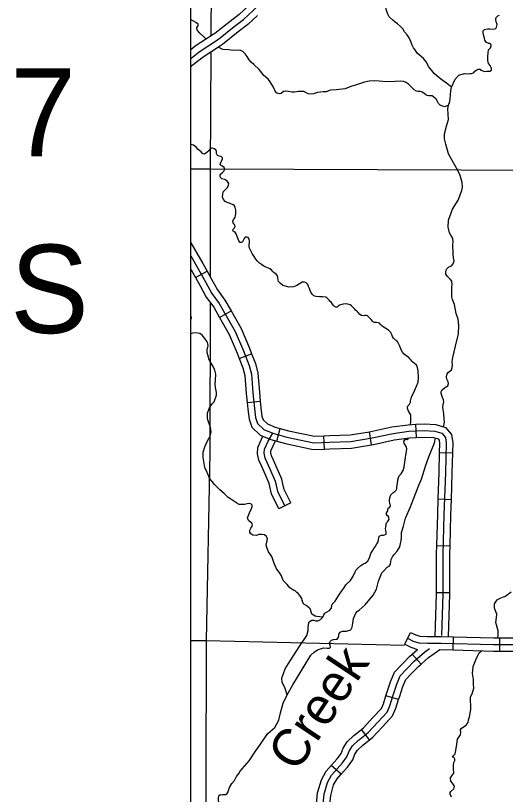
# Model space of a CAD drawing. Extents: x 813775 to 1157140, y 1757555 to 1979907.
# Drawn here: x 908560 to 919670, y 1830487 to 1848131 of the extents above; entities that cross this region are included whole.
import ezdxf

# ---------------------------------------------------------------- set-up
doc = ezdxf.new("R2010")
doc.units = 0
for name, color, linetype in [('Level 31', 7, 'Continuous'), ('Level 32', 7, 'Continuous'), ('Level 35', 7, 'Continuous'), ('Level 45', 7, 'Continuous'), ('Level 5', 7, 'Continuous'), ('R_Draft', 7, 'Continuous')]:
    doc.layers.add(name, color=color, linetype=linetype)

msp = doc.modelspace()

# ---------------------------------------------------------------- linework, layer by layer
at = {"layer": 'Level 31'}
msp.add_line((913206, 1847448), (913206, 1847448), dxfattribs=at)
for points in [[(913839, 1848351), (913631, 1848158), (913427, 1847997), (913077, 1847722), (913042, 1847699)], [(914043, 1848131), (913825, 1847930), (913612, 1847762), (913252, 1847478), (913206, 1847448)], [(913042, 1847699), (912636, 1847435), (912532, 1847351)], [(913206, 1847448), (912813, 1847192), (912560, 1846989), (912532, 1846967)], [(917450, 1834023), (917579, 1833961), (917703, 1833921), (917903, 1833912), (918142, 1833916)], [(918142, 1833916), (918210, 1833916), (919402, 1833885), (920055, 1833881), (920618, 1833885), (920845, 1833912), (921089, 1833965), (921240, 1834010)]]:
    msp.add_lwpolyline(points, dxfattribs=at)
at = {"layer": 'Level 32'}
for p, q in [((912640, 1842196), (912902, 1842341)), ((913186, 1841292), (913447, 1841440)), ((913633, 1840363), (913913, 1840469)), ((913810, 1839369), (914108, 1839399)), ((917656, 1838573), (917641, 1838872)), ((914484, 1838488), (914562, 1838778)), ((916632, 1838408), (916583, 1838704)), ((915564, 1838310), (915552, 1838610)), ((918169, 1838235), (918469, 1838227)), ((918138, 1837180), (918438, 1837171)), ((918105, 1836124), (918405, 1836116)), ((918100, 1835064), (918400, 1835064)), ((917385, 1833888), (917516, 1834158)), ((918482, 1833759), (918489, 1834059)), ((919540, 1833734), (919542, 1834034)), ((917755, 1833439), (917556, 1833664)), ((917247, 1832636), (916960, 1832723)), ((916589, 1831725), (916404, 1831961)), ((915943, 1830942), (915719, 1831141))]:
    msp.add_line(p, q, dxfattribs=at)
for points in [[(912725, 1847313), (913164, 1847600), (913519, 1847880), (913728, 1848044), (913959, 1848257), (914070, 1848377), (914460, 1848793), (914828, 1849122), (915197, 1849397), (915490, 1849553), (916023, 1849828), (916848, 1850202), (917260, 1850408), (917789, 1850804), (918401, 1851252), (919258, 1851906), (919871, 1852368), (920115, 1852546), (920266, 1852639), (920426, 1852726), (920697, 1852828)], [(912532, 1847159), (912725, 1847313)], [(912532, 1842983), (912804, 1842518), (912902, 1842341)], [(912532, 1842686), (912674, 1842444), (912874, 1842084), (913011, 1841835)], [(912532, 1842389), (912544, 1842369), (912640, 1842196)], [(912902, 1842341), (913005, 1842156), (913138, 1841916), (913306, 1841687), (913447, 1841440)], [(912640, 1842196), (912743, 1842011), (912885, 1841754), (913054, 1841524), (913186, 1841292)], [(913011, 1841835), (913180, 1841605), (913540, 1840974), (913726, 1840539), (913855, 1840201), (913908, 1840005), (913939, 1839583), (913975, 1839228), (914001, 1839023)], [(913447, 1841440), (913674, 1841041), (913865, 1840595), (913913, 1840469)], [(913186, 1841292), (913405, 1840907), (913587, 1840483), (913633, 1840363)], [(913913, 1840469), (913998, 1840248), (914057, 1840031), (914089, 1839596), (914108, 1839399)], [(913633, 1840363), (913712, 1840154), (913760, 1839980), (913790, 1839570), (913810, 1839369)], [(914108, 1839399), (914124, 1839245), (914148, 1839059), (914179, 1838975), (914276, 1838879), (914444, 1838810), (914562, 1838778)], [(913810, 1839369), (913826, 1839211), (913855, 1838987), (913920, 1838809), (914107, 1838624), (914347, 1838525), (914484, 1838488)], [(914001, 1839023), (914049, 1838892), (914191, 1838752), (914396, 1838667), (914715, 1838581), (915324, 1838450), (915683, 1838465), (916163, 1838483), (916647, 1838563), (917122, 1838665), (917477, 1838714), (917828, 1838732), (918067, 1838718), (918227, 1838670), (918307, 1838576), (918325, 1838443), (918307, 1837776)], [(916583, 1838704), (916619, 1838710), (917096, 1838813), (917463, 1838863), (917641, 1838872)], [(917641, 1838872), (917828, 1838882), (918094, 1838867), (918313, 1838800), (918450, 1838640), (918475, 1838451), (918469, 1838227)], [(914562, 1838778), (914751, 1838726), (915336, 1838600), (915552, 1838610)], [(915552, 1838610), (915677, 1838615), (916148, 1838632), (916583, 1838704)], [(916632, 1838408), (916675, 1838415), (917148, 1838517), (917491, 1838565), (917656, 1838573)], [(917656, 1838573), (917827, 1838582), (918041, 1838570), (918142, 1838539), (918164, 1838512), (918175, 1838435), (918169, 1838235)], [(914484, 1838488), (914680, 1838435), (915311, 1838299), (915564, 1838310)], [(915564, 1838310), (915689, 1838315), (916178, 1838333), (916632, 1838408)], [(918169, 1838235), (918157, 1837781), (918138, 1837180)], [(918469, 1838227), (918457, 1837772), (918438, 1837171)], [(918307, 1837776), (918276, 1836820), (918250, 1835927), (918250, 1835020), (918223, 1834085)], [(918138, 1837180), (918126, 1836825), (918105, 1836124)], [(918438, 1837171), (918426, 1836816), (918405, 1836116)], [(918105, 1836124), (918100, 1835929), (918100, 1835064)], [(918405, 1836116), (918400, 1835925), (918400, 1835064)], [(918100, 1835064), (918100, 1835023), (918072, 1834065)], [(918400, 1835064), (918400, 1835018), (918372, 1834062)], [(917516, 1834158), (917635, 1834101), (917730, 1834070), (917905, 1834062), (918140, 1834066), (918211, 1834066), (918489, 1834059)], [(918489, 1834059), (919404, 1834035), (919542, 1834034)], [(919542, 1834034), (920054, 1834031), (920596, 1834035)], [(915514, 1830054), (915559, 1830494), (915634, 1830760), (915728, 1830925), (915972, 1831200), (916074, 1831342), (916123, 1831466), (916198, 1831586), (916327, 1831710), (916553, 1831888), (916775, 1832123), (916984, 1832350), (917046, 1832490), (917122, 1832739), (917206, 1832988), (917281, 1833170), (917441, 1833339), (917601, 1833503), (917832, 1833708), (917950, 1833789)], [(917385, 1833888), (917523, 1833821), (917678, 1833772)], [(917556, 1833664), (917678, 1833772)], [(917755, 1833439), (917925, 1833589), (918183, 1833767)], [(918183, 1833767), (918482, 1833759)], [(918482, 1833759), (919399, 1833735), (919540, 1833734)], [(916960, 1832723), (916979, 1832785), (917066, 1833041), (917153, 1833253), (917333, 1833443), (917497, 1833612), (917556, 1833664)], [(919540, 1833734), (920055, 1833731), (920598, 1833735)], [(917247, 1832636), (917264, 1832693), (917346, 1832935), (917409, 1833087), (917550, 1833235), (917705, 1833395), (917755, 1833439)], [(916404, 1831961), (916452, 1831999), (916666, 1832226), (916857, 1832433), (916905, 1832542), (916960, 1832723)], [(916589, 1831725), (916655, 1831777), (916885, 1832021), (917111, 1832266), (917187, 1832438), (917247, 1832636)], [(915719, 1831141), (915854, 1831294), (915941, 1831415), (915988, 1831534), (916081, 1831681), (916228, 1831823), (916404, 1831961)], [(915943, 1830942), (916089, 1831106), (916206, 1831270), (916257, 1831397), (916315, 1831490), (916426, 1831597), (916589, 1831725)], [(915366, 1830077), (915411, 1830522), (915495, 1830818), (915605, 1831012), (915719, 1831141)], [(915664, 1830047), (915707, 1830465), (915774, 1830702), (915850, 1830837), (915943, 1830942)]]:
    msp.add_lwpolyline(points, dxfattribs=at)
at = {"layer": 'Level 35'}
for points in [[(917117, 1848023), (917032, 1848102), (917008, 1848150), (916972, 1848247), (916940, 1848371), (916911, 1848473), (916858, 1848541), (916807, 1848599), (916776, 1848657), (916773, 1848727), (916814, 1848810), (916831, 1848902), (916829, 1848977), (916829, 1849016), (916834, 1849064), (916826, 1849108)], [(912670, 1847833), (912673, 1847859), (912699, 1847897), (912699, 1847936), (912651, 1847977), (912544, 1848031), (912532, 1848038)], [(919480, 1847929), (919463, 1847988), (919449, 1848046), (919456, 1848090), (919495, 1848126), (919536, 1848141)], [(917766, 1847193), (917713, 1847238), (917664, 1847276), (917626, 1847354), (917587, 1847400), (917558, 1847461), (917526, 1847545), (917490, 1847623), (917444, 1847693), (917383, 1847764), (917340, 1847832), (917291, 1847882), (917224, 1847941), (917170, 1847982), (917117, 1848023)], [(918533, 1846689), (918616, 1846783), (918739, 1846817), (918802, 1846814), (918873, 1846819), (918897, 1846822), (918936, 1846831), (918962, 1846851), (918979, 1846868), (919020, 1846904), (919054, 1846919), (919093, 1846914), (919112, 1846894), (919202, 1846865), (919248, 1846868), (919277, 1846868), (919316, 1846873), (919350, 1846897), (919354, 1846943), (919323, 1847001), (919287, 1847047), (919270, 1847110), (919270, 1847202), (919289, 1847353), (919333, 1847403), (919347, 1847447), (919345, 1847466), (919333, 1847486), (919311, 1847498), (919294, 1847500), (919241, 1847520), (919202, 1847573), (919190, 1847651), (919173, 1847692), (919163, 1847748), (919163, 1847786), (919192, 1847815), (919260, 1847830), (919316, 1847828), (919393, 1847820), (919449, 1847840), (919466, 1847869), (919480, 1847929)], [(912884, 1847596), (912827, 1847646), (912738, 1847729), (912684, 1847792), (912670, 1847833)], [(913623, 1847344), (913493, 1847341), (913394, 1847353), (913258, 1847360), (913154, 1847414)], [(914640, 1846412), (914582, 1846363), (914529, 1846358), (914478, 1846380), (914447, 1846421), (914408, 1846511), (914360, 1846591), (914333, 1846629), (914294, 1846683), (914238, 1846736), (914185, 1846784), (914142, 1846833), (914081, 1846910), (913960, 1847022), (913902, 1847078), (913858, 1847131), (913810, 1847204), (913766, 1847262), (913713, 1847318), (913665, 1847342), (913623, 1847344)], [(918446, 1846512), (918333, 1846599), (918260, 1846655), (918170, 1846723), (918057, 1846818), (917998, 1846890), (917928, 1846978), (917877, 1847079), (917810, 1847159), (917766, 1847193)], [(917167, 1846637), (916974, 1846632), (916807, 1846645), (916705, 1846654), (916581, 1846645), (916472, 1846623), (916293, 1846560)], [(918379, 1846099), (918298, 1846063), (918242, 1846077), (918191, 1846104), (918150, 1846140), (918128, 1846182), (918097, 1846235), (918046, 1846283), (918005, 1846312), (917930, 1846312), (917898, 1846317), (917862, 1846334), (917818, 1846373), (917783, 1846396), (917743, 1846407), (917688, 1846407), (917655, 1846418), (917598, 1846451), (917533, 1846514), (917472, 1846577), (917404, 1846620), (917361, 1846640), (917283, 1846642), (917167, 1846637)], [(918335, 1845628), (918377, 1845778), (918369, 1845901), (918360, 1846020), (918379, 1846099), (918406, 1846182), (918413, 1846243), (918429, 1846424), (918446, 1846512), (918533, 1846689)], [(916293, 1846560), (916167, 1846521), (916032, 1846470), (915831, 1846446), (915710, 1846441), (915673, 1846436), (915613, 1846402), (915535, 1846400), (915472, 1846397), (915409, 1846385), (915317, 1846356), (915238, 1846351), (915194, 1846359)], [(915194, 1846359), (915100, 1846409), (915027, 1846414), (914977, 1846412), (914887, 1846397), (914831, 1846392), (914744, 1846412), (914679, 1846419), (914640, 1846412)], [(918695, 1844241), (918687, 1844346), (918641, 1844510), (918587, 1844620), (918457, 1844862), (918379, 1844999), (918316, 1845219), (918286, 1845339), (918289, 1845449), (918335, 1845628)], [(913207, 1844743), (913200, 1844762), (913229, 1844830), (913253, 1844885), (913253, 1844910), (913221, 1844941), (913175, 1844944), (913139, 1844960), (913115, 1845007), (913115, 1845053), (913098, 1845087), (913061, 1845111), (913023, 1845128), (913011, 1845125), (912977, 1845113), (912953, 1845077), (912897, 1845026), (912844, 1844992), (912810, 1845002), (912766, 1845043), (912698, 1845099), (912655, 1845150), (912597, 1845196), (912532, 1845212)], [(913270, 1844141), (913362, 1844232), (913391, 1844280), (913398, 1844329), (913362, 1844382), (913308, 1844418), (913238, 1844433), (913209, 1844462), (913197, 1844493), (913202, 1844532), (913246, 1844566), (913284, 1844605), (913308, 1844651), (913289, 1844690), (913241, 1844724), (913207, 1844743)], [(918367, 1843336), (918382, 1843497), (918467, 1843745), (918594, 1843950), (918677, 1844166), (918695, 1844241)], [(913496, 1843844), (913424, 1843873), (913361, 1843897), (913315, 1843920), (913276, 1843962), (913256, 1844018), (913258, 1844084), (913270, 1844141)], [(913522, 1843399), (913508, 1843412), (913492, 1843432), (913486, 1843469), (913499, 1843509), (913537, 1843556), (913548, 1843603), (913556, 1843643), (913554, 1843724), (913544, 1843780), (913526, 1843820), (913496, 1843844)], [(913534, 1843229), (913492, 1843243), (913486, 1843263), (913492, 1843292), (913522, 1843323), (913539, 1843355), (913535, 1843382), (913522, 1843399)], [(918458, 1842039), (918452, 1842117), (918413, 1842161), (918355, 1842217), (918318, 1842271), (918316, 1842327), (918330, 1842384), (918379, 1842428), (918450, 1842462), (918484, 1842506), (918504, 1842572), (918489, 1842641), (918487, 1842726), (918482, 1842812), (918476, 1842865), (918479, 1842947), (918484, 1843005), (918477, 1843071), (918465, 1843113), (918433, 1843157), (918404, 1843208), (918367, 1843336)], [(913854, 1842936), (913866, 1842988), (913867, 1843017), (913858, 1843068), (913837, 1843100), (913804, 1843112), (913769, 1843109), (913744, 1843081), (913719, 1843036), (913704, 1843005), (913679, 1842987), (913655, 1842990), (913626, 1843030), (913587, 1843125), (913560, 1843186), (913534, 1843229)], [(914296, 1842408), (914218, 1842441), (914188, 1842456), (914138, 1842488), (914091, 1842521), (914046, 1842569), (914012, 1842614), (913973, 1842675), (913923, 1842741), (913886, 1842815), (913868, 1842858), (913854, 1842898), (913854, 1842936)], [(914516, 1842137), (914510, 1842200), (914499, 1842235), (914478, 1842267), (914448, 1842290), (914414, 1842312), (914397, 1842325), (914385, 1842342), (914361, 1842371), (914325, 1842393), (914296, 1842408)], [(915059, 1842090), (915000, 1842056), (914939, 1842013), (914862, 1841983), (914767, 1841976), (914623, 1842013), (914559, 1842070), (914525, 1842107), (914516, 1842137)], [(915673, 1841686), (915622, 1841733), (915597, 1841750), (915525, 1841760), (915454, 1841762), (915379, 1841768), (915327, 1841784), (915284, 1841823), (915250, 1841878), (915228, 1841949), (915204, 1841994), (915186, 1842042), (915149, 1842078), (915109, 1842091), (915059, 1842090)], [(918457, 1841762), (918452, 1841843), (918457, 1841977), (918458, 1842039)], [(916269, 1841457), (916244, 1841487), (916223, 1841511), (916176, 1841554), (916148, 1841576), (916099, 1841593), (916043, 1841599), (915992, 1841593), (915910, 1841574), (915884, 1841554), (915857, 1841528), (915824, 1841524), (915795, 1841538), (915769, 1841564), (915749, 1841596), (915727, 1841627), (915698, 1841657), (915673, 1841686)], [(918477, 1840383), (918540, 1840638), (918602, 1840920), (918609, 1841111), (918597, 1841255), (918550, 1841382), (918511, 1841588), (918472, 1841695), (918457, 1841762)], [(912532, 1841239), (912536, 1841244), (912551, 1841282), (912544, 1841316), (912532, 1841331)], [(916813, 1841162), (916786, 1841171), (916745, 1841174), (916701, 1841175), (916676, 1841187), (916653, 1841209), (916624, 1841244), (916601, 1841272), (916575, 1841301), (916545, 1841328), (916521, 1841337), (916479, 1841337), (916446, 1841329), (916407, 1841336), (916370, 1841362), (916331, 1841404), (916297, 1841437), (916269, 1841457)], [(917308, 1840555), (917276, 1840641), (917228, 1840731), (917215, 1840754), (917198, 1840770), (917180, 1840779), (917154, 1840801), (917132, 1840824), (917107, 1840859), (917086, 1840919), (917067, 1840949), (917017, 1841003), (916954, 1841039), (916894, 1841077), (916862, 1841108), (916838, 1841132), (916813, 1841162)], [(912903, 1840738), (912849, 1840815), (912793, 1840892), (912737, 1840928), (912640, 1840945), (912573, 1840936), (912532, 1840921)], [(912936, 1840389), (912907, 1840495), (912907, 1840556), (912926, 1840653), (912924, 1840697), (912914, 1840726), (912903, 1840738)], [(917475, 1840384), (917417, 1840422), (917371, 1840462), (917334, 1840506), (917308, 1840555)], [(913064, 1839383), (913117, 1839529), (913120, 1839590), (913093, 1839702), (913083, 1839791), (913093, 1839869), (913100, 1840007), (913079, 1840097), (913042, 1840179), (912972, 1840293), (912945, 1840344), (912936, 1840389)], [(917692, 1840030), (917689, 1840086), (917679, 1840155), (917652, 1840209), (917603, 1840253), (917570, 1840276), (917554, 1840293), (917528, 1840326), (917503, 1840357), (917475, 1840384)], [(918360, 1839745), (918379, 1839793), (918374, 1839834), (918340, 1839893), (918330, 1839950), (918347, 1840013), (918377, 1840052), (918443, 1840106), (918465, 1840160), (918467, 1840211), (918462, 1840295), (918477, 1840383)], [(917585, 1839577), (917656, 1839735), (917692, 1839824), (917700, 1839925), (917695, 1839982), (917692, 1840030)], [(918257, 1838817), (918274, 1838842), (918291, 1838920), (918281, 1838996), (918269, 1839111), (918252, 1839256), (918257, 1839312), (918272, 1839383), (918264, 1839427), (918242, 1839478), (918210, 1839571), (918210, 1839611), (918228, 1839647), (918291, 1839694), (918360, 1839745)], [(917523, 1838926), (917521, 1838998), (917526, 1839043), (917521, 1839086), (917512, 1839108), (917482, 1839153), (917461, 1839192), (917451, 1839232), (917451, 1839261), (917464, 1839299), (917492, 1839331), (917516, 1839371), (917520, 1839387), (917518, 1839406), (917521, 1839436), (917532, 1839461), (917557, 1839522), (917585, 1839577)], [(912912, 1838497), (912977, 1838605), (912999, 1838692), (912984, 1838801), (912914, 1838998), (912914, 1839121), (912948, 1839228), (913016, 1839335), (913064, 1839383)], [(917516, 1838866), (917523, 1838926)], [(917409, 1838181), (917425, 1838255), (917435, 1838314), (917422, 1838368), (917396, 1838406), (917372, 1838438), (917369, 1838480), (917386, 1838517), (917408, 1838532), (917443, 1838530), (917464, 1838540), (917470, 1838562)], [(917766, 1837631), (917866, 1837943), (917932, 1838136), (918064, 1838455), (918086, 1838556)], [(912967, 1837635), (912904, 1837777), (912851, 1837896), (912817, 1838119), (912817, 1838243), (912849, 1838359), (912912, 1838497)], [(917308, 1837748), (917348, 1837825), (917374, 1837908), (917391, 1838014), (917406, 1838123), (917409, 1838181)], [(913699, 1837051), (913633, 1837054), (913580, 1837088), (913507, 1837129), (913439, 1837172), (913381, 1837216), (913287, 1837303), (913190, 1837388), (913069, 1837504), (913016, 1837572), (912967, 1837635)], [(917223, 1837533), (917230, 1837611), (917244, 1837667), (917263, 1837704), (917308, 1837748)], [(917306, 1836235), (917311, 1836317), (917316, 1836422), (917355, 1836567), (917406, 1836745), (917514, 1837000), (917702, 1837489), (917766, 1837631)], [(917048, 1836995), (917063, 1837032), (917063, 1837038), (917045, 1837070), (917042, 1837145), (917051, 1837217), (917071, 1837272), (917115, 1837317), (917165, 1837352), (917189, 1837380), (917208, 1837413), (917208, 1837464), (917223, 1837533)], [(913699, 1837051), (913694, 1837051)], [(914245, 1836134), (914262, 1836201), (914274, 1836274), (914250, 1836330), (914202, 1836364), (914144, 1836376), (914076, 1836378), (914025, 1836354), (913940, 1836357), (913899, 1836388), (913875, 1836427), (913870, 1836475), (913897, 1836521), (913921, 1836550), (913931, 1836594), (913918, 1836630), (913885, 1836657), (913839, 1836691), (913822, 1836754), (913863, 1836863), (913911, 1836962), (913928, 1837013), (913923, 1837042), (913894, 1837069), (913851, 1837074), (913812, 1837068), (913751, 1837057), (913699, 1837051)], [(916963, 1836618), (916969, 1836638), (916998, 1836662), (917007, 1836684), (917030, 1836725), (917028, 1836750), (917026, 1836764), (917023, 1836771), (917009, 1836788), (916990, 1836803), (916976, 1836827), (916973, 1836864), (916999, 1836908), (917005, 1836949), (917023, 1836976), (917048, 1836995)], [(916785, 1836211), (916793, 1836258), (916796, 1836289), (916802, 1836320), (916821, 1836345), (916856, 1836361), (916901, 1836361), (916928, 1836365), (916962, 1836384), (916965, 1836406), (916964, 1836428), (916958, 1836468), (916952, 1836512), (916954, 1836538), (916963, 1836577), (916963, 1836618)], [(916901, 1835547), (916986, 1835633), (917030, 1835660), (917064, 1835701), (917074, 1835760), (917077, 1835807), (917106, 1835868), (917152, 1835931), (917216, 1835995), (917272, 1836098), (917292, 1836169), (917306, 1836235)], [(914630, 1835336), (914592, 1835439), (914553, 1835499), (914473, 1835611), (914415, 1835737), (914371, 1835880), (914294, 1835982), (914255, 1836079), (914245, 1836134)], [(916487, 1835726), (916528, 1835757), (916546, 1835772), (916594, 1835871), (916619, 1835941), (916651, 1836007), (916687, 1836056), (916717, 1836096), (916755, 1836161), (916785, 1836211)], [(916048, 1835234), (916153, 1835332), (916215, 1835434), (916259, 1835533), (916283, 1835576), (916311, 1835608), (916391, 1835673), (916410, 1835691), (916447, 1835709), (916487, 1835726)], [(916356, 1834659), (916492, 1834778), (916668, 1835003), (916747, 1835137), (916791, 1835319), (916869, 1835507), (916901, 1835547)], [(915066, 1834851), (915049, 1834926), (915006, 1834996), (914967, 1835035), (914940, 1835064), (914904, 1835096), (914870, 1835103), (914780, 1835166), (914720, 1835241), (914630, 1835336)], [(915197, 1834246), (915202, 1834345), (915221, 1834394), (915278, 1834438), (915326, 1834433), (915361, 1834421), (915412, 1834421), (915476, 1834451), (915525, 1834502), (915551, 1834558), (915571, 1834592), (915630, 1834624), (915681, 1834654), (915723, 1834707), (915730, 1834771), (915740, 1834796), (915808, 1834867), (915845, 1834923), (915908, 1835021), (915960, 1835102), (916004, 1835158), (916048, 1835234)], [(919498, 1834034), (919506, 1834103), (919506, 1834196), (919454, 1834380), (919467, 1834494), (919472, 1834571), (919418, 1834709), (919418, 1834802), (919480, 1834892), (919552, 1834934), (919625, 1834960), (919656, 1834973), (919803, 1835075)], [(915525, 1834502), (915393, 1834514), (915357, 1834524), (915279, 1834572), (915250, 1834674), (915245, 1834686), (915221, 1834715), (915149, 1834764), (915095, 1834800), (915066, 1834851), (915069, 1834887)], [(915681, 1833803), (915703, 1833826), (915693, 1833868), (915683, 1833915), (915693, 1833954), (915723, 1833983), (915771, 1833993), (915855, 1834005), (915881, 1834047), (915899, 1834130), (915921, 1834162), (915977, 1834184), (916062, 1834186), (916165, 1834216), (916197, 1834279), (916209, 1834367), (916221, 1834473), (916251, 1834541), (916275, 1834595), (916317, 1834639), (916356, 1834659)], [(914721, 1832743), (914674, 1832886), (914608, 1833028), (914598, 1833118), (914677, 1833334), (914784, 1833512), (915009, 1833855), (915163, 1834087), (915197, 1834200), (915197, 1834246)], [(914721, 1832743), (914845, 1832971), (915080, 1833358), (915254, 1833642), (915334, 1833713), (915405, 1833762), (915540, 1833806), (915623, 1833799), (915681, 1833803)], [(918917, 1832765), (918950, 1832893), (918948, 1832981), (918943, 1833087), (918922, 1833224), (918938, 1833387), (919000, 1833537), (919033, 1833620), (919077, 1833693), (919127, 1833742)], [(914157, 1831693), (914283, 1831867), (914442, 1832006), (914530, 1832170), (914567, 1832332), (914628, 1832555), (914721, 1832743)], [(918544, 1831480), (918568, 1831628), (918586, 1831737), (918650, 1831833), (918658, 1831900), (918653, 1831949), (918671, 1831986), (918780, 1832053), (918826, 1832113), (918829, 1832177), (918857, 1832245), (918888, 1832410), (918886, 1832516), (918881, 1832589), (918878, 1832700), (918917, 1832765)], [(913568, 1830890), (913631, 1830972), (913648, 1831003), (913861, 1831246), (914003, 1831463), (914098, 1831605), (914157, 1831693)], [(918449, 1830426), (918418, 1830494), (918415, 1830530), (918433, 1830556), (918500, 1830615), (918511, 1830675), (918469, 1830740), (918431, 1830789), (918420, 1830859), (918451, 1830908), (918503, 1830967), (918493, 1831076), (918495, 1831154), (918498, 1831213), (918519, 1831255), (918519, 1831288), (918506, 1831312), (918487, 1831327), (918472, 1831340), (918475, 1831356), (918498, 1831377), (918526, 1831405), (918539, 1831444), (918544, 1831480)], [(913374, 1830531), (913408, 1830640), (913462, 1830731), (913525, 1830803), (913568, 1830890)], [(913050, 1829920), (913112, 1830001), (913140, 1830066), (913156, 1830137), (913171, 1830184), (913174, 1830246), (913166, 1830370), (913165, 1830416), (913172, 1830445), (913190, 1830475), (913212, 1830481), (913256, 1830482), (913323, 1830487), (913358, 1830509), (913374, 1830531)]]:
    msp.add_lwpolyline(points, dxfattribs=at)
at = {"layer": 'Level 45'}
msp.add_line((914801, 1837089), (914532, 1836957), dxfattribs=at)
for points in [[(914134, 1837933), (914075, 1838060), (914044, 1838206), (914058, 1838346), (914169, 1838599)], [(914667, 1837023), (914507, 1837347), (914476, 1837494), (914458, 1837578), (914334, 1837858), (914218, 1838107), (914196, 1838214), (914205, 1838307), (914285, 1838490), (914396, 1838667)], [(914406, 1838059), (914361, 1838155), (914347, 1838222), (914352, 1838269), (914452, 1838497)], [(914801, 1837089), (914650, 1837397), (914622, 1837525), (914601, 1837625), (914470, 1837920), (914406, 1838059)], [(914532, 1836957), (914364, 1837298), (914329, 1837463), (914314, 1837532), (914197, 1837796), (914134, 1837933)]]:
    msp.add_lwpolyline(points, dxfattribs=at)
at = {"layer": 'Level 5'}
for points in [[(913038, 1855215), (912991, 1847666)], [(912988, 1847306), (912972, 1844659)], [(912532, 1844657), (912972, 1844659)], [(912972, 1844659), (912970, 1842219)], [(912972, 1844659), (920561, 1844630)], [(912970, 1841638), (912967, 1838234), (912882, 1833970)], [(912532, 1833973), (912882, 1833970)], [(912882, 1833970), (912871, 1827400)], [(912882, 1833970), (917377, 1833868)]]:
    msp.add_lwpolyline(points, dxfattribs=at)
at = {"layer": 'R_Draft'}
msp.add_lwpolyline([(912532, 1880709), (1062535, 1880709), (1062535, 1798155), (912532, 1798155)], close=True, dxfattribs=at)

# ---------------------------------------------------------------- texts
at = {"layer": 'Level 35'}
msp.add_text('Creek', height=844.8, rotation=56.3345, dxfattribs=at).set_placement((914936, 1830965))
at = {"layer": 'R_Draft'}
for s, p in [('7', (908439, 1844939)), ('S', (908438, 1840939))]:
    msp.add_text(s, height=2000, dxfattribs=at).set_placement(p)

doc.saveas('drawing.dxf')
